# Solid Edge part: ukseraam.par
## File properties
Author: Mac
Template: Normal.par
Last saved by: Mac
Revision: 2
Application: Solid Edge
Material: Aluminum, 1060
Face Style: Aluminum
Fill Style: ANSI38(Aluminum)
Virtual Style: Polished aluminum
Coef. of Thermal Exp: 2.3e-05
Thermal Conductivity: 221.0
Specific Heat: 920.0
Modulus of Elasticity: 68947570000.0
Poission's Ratio: 0.33
Yield Stress: 27579028.0
Ultimate Stress: 68947570.0
Elongation: 0.0
Accuracy: 0,990
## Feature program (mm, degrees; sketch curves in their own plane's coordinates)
sketch for "unnamed Protrusion 1" #1 plane through (0, 0, 0) normal (0, 0, 1) x-axis (1, 0, 0)
sketch for "unnamed Protrusion 1" #2 plane through (0, 0, 0) normal (0, 0, 1) x-axis (1, 0, 0)
  line (23.3, 19.35) -> (23.3, -19.35)
  line (-23.3, -19.35) -> (23.3, -19.35)
  line (-23.3, 19.35) -> (-23.3, -19.35)
  line (-23.3, 19.35) -> (23.3, 19.35)
sketch for "unnamed Protrusion 1" #3 plane through (0, 0, 0) normal (0, 0, 1) x-axis (1, 0, 0)
sketch for "unnamed Protrusion 1" #4 plane through (0, 0, 0) normal (0, 0, 1) x-axis (1, 0, 0)
  line (22.5, 18.55) -> (22.5, -18.55)
  line (0.4, -18.55) -> (22.5, -18.55)
  line (0.4, 18.55) -> (0.4, -18.55)
  line (0.4, 18.55) -> (22.5, 18.55)
extrude "unnamed Protrusion 1" add finite 0.6 along +normal
thinwall "Thinwall_2"  Thickness = 0.04 mm
sketch for "ExtrudedProtrusion_2" #1 plane through (0, 0, 0.6) normal (0, 0, 1) x-axis (1, 0, 0)
sketch for "ExtrudedProtrusion_2" #2 plane through (0, 0, 0.6) normal (0, 0, 1) x-axis (1, 0, 0)
  line (-22.5, 18.55) -> (22.5, 18.55)
  line (22.5, 18.55) -> (22.5, -18.55)
  line (22.5, -18.55) -> (-22.5, -18.55)
  line (-22.5, -18.55) -> (-22.5, 18.55)
extrude "ExtrudedProtrusion_2" add finite 0.6 along +normal
thinwall "Thinwall_3"  Thickness = 0.04 mm
sketch for "ExtrudedProtrusion_3" plane through (0, 0, 0.3) normal (0, 0, 1) x-axis (1, 0, 0)
  line (-22.5, -0.4) -> (-0.4, -0.4)
  line (-0.4, -0.4) -> (-0.4, -18.55)
  line (-0.4, -18.55) -> (-22.5, -18.55)
  line (-22.5, -18.55) -> (-22.5, -0.4)
extrude "ExtrudedProtrusion_3" add finite 0.04 symmetric  Profile_Plane1_Distance = 0.3 mm
sketch for "ExtrudedProtrusion_4" plane through (0, 0, 0.3) normal (0, 0, 1) x-axis (1, 0, 0)
  line (-22.5, 18.55) -> (-22.5, 0.4)
  line (-22.5, 0.4) -> (-0.4, 0.4)
  line (-0.4, 0.4) -> (-0.4, 18.55)
  line (-0.4, 18.55) -> (-22.5, 18.55)
extrude "ExtrudedProtrusion_4" add finite 0.2 symmetric  Profile_Plane1_Distance = 0.3 mm
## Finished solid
Body 1: solid body, 58 faces, 144 edges, 96 vertices.
  Faces by surface: plane 58
  Edges by curve: line 144
Bounding box of the edges (mm): 46.600 x 38.700 x 1.200, from (-23.3, -19.35, 0) to (23.3, 19.35, 1.2).
Planar faces by outward normal: +x 12, +y 12, +z 5, -x 12, -y 12, -z 5
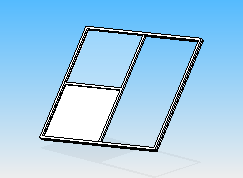
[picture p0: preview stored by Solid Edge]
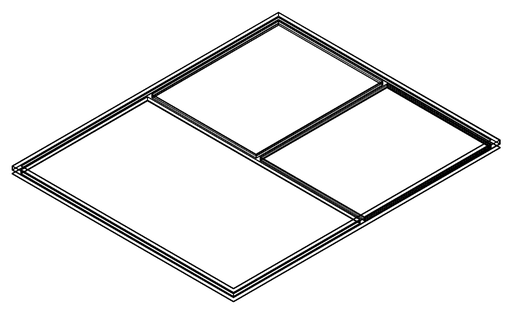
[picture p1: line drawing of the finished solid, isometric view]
